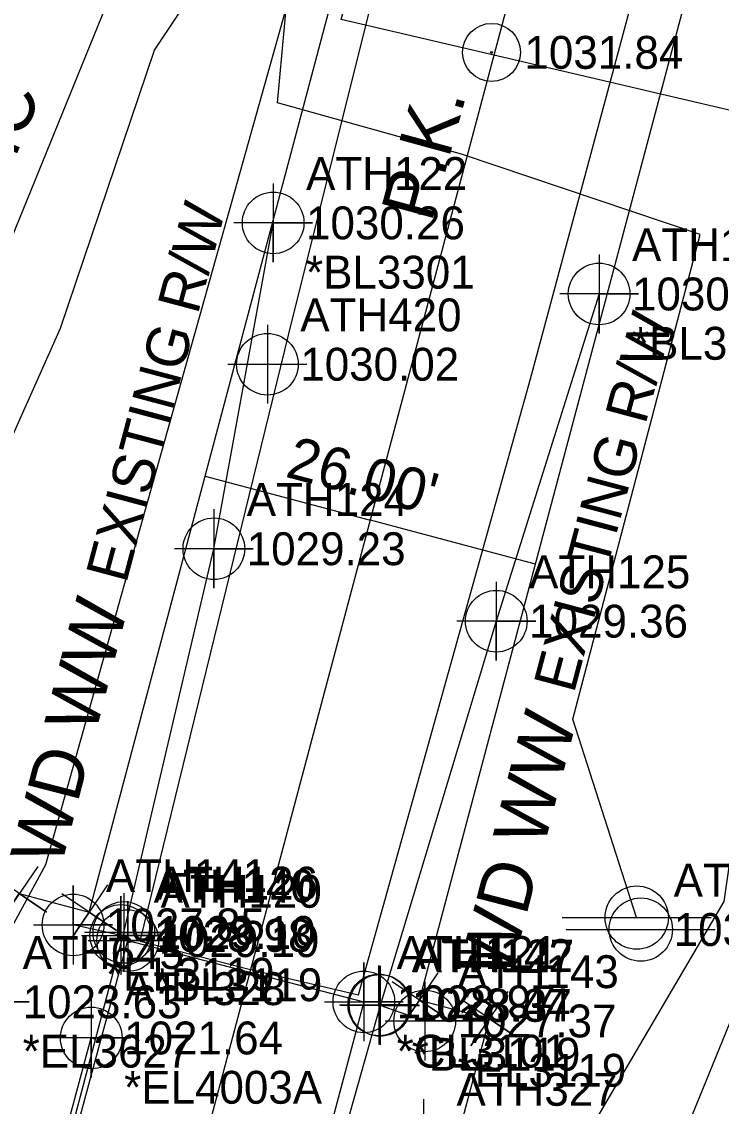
# Model space of a CAD drawing. Extents: x 1212084 to 1214478, y 765637 to 767408.
# Drawn here: x 1213319 to 1213372.2, y 766500.6 to 766583.1 of the extents above; entities that cross this region are included whole.
import ezdxf

# ---------------------------------------------------------------- set-up
doc = ezdxf.new("R2010")
doc.units = 0
for name, color, linetype in [('Cogo Default Point CELL', 7, 'Continuous'), ('COGO Default Point Elevation', 7, 'Continuous'), ('COGO Default Point Number', 7, 'Continuous'), ('Default', 7, 'Continuous'), ('Exist DTM Drainline', 7, 'Continuous'), ('Exist DTM Drainline Cogo Comment', 7, 'Continuous'), ('Exist DTM Drainline Cogo Elevation', 7, 'Continuous'), ('Exist DTM Drainline Cogo Number', 7, 'Continuous'), ('Exist DTM Drainline Cogo Point CELL', 7, 'Continuous'), ('Exist Environmental Wetland Boundary Cogo Comment', 7, 'Continuous'), ('Exist Environmental Wetland Boundary Cogo Elevation', 7, 'Continuous'), ('Exist Environmental Wetland Boundary Cogo Number', 7, 'Continuous'), ('Exist Environmental Wetland Boundary Cogo Point CELL', 7, 'Continuous'), ('Exist Guardrail', 7, 'Continuous'), ('Exist Guardrail Cogo Comment', 7, 'Continuous'), ('Exist Guardrail Cogo Elevation', 7, 'Continuous'), ('Exist Guardrail Cogo Number', 7, 'Continuous'), ('Exist Guardrail Cogo Point CELL', 7, 'Continuous'), ('Exist Horizontal Alignment', 7, 'Continuous'), ('Exist Hydro Stream or Body of Water', 7, 'Continuous'), ('Exist Other Culture Fence Line', 7, 'Continuous'), ('Exist Other Culture Fence Line Text', 7, 'Continuous'), ('Exist Property Corner CELL', 7, 'Continuous'), ('Exist Property Iron Pin CELL', 7, 'Continuous'), ('Exist Property Iron Pin Cogo Elevation', 7, 'Continuous'), ('Exist Property Iron Pin Text', 7, 'Continuous'), ('Exist Right of Way Line', 7, 'Continuous'), ('Exist Right of Way Line Text', 7, 'Continuous'), ('Exist Right of Way Width CELL', 7, 'Continuous'), ('Exist Roads EOP', 7, 'Continuous'), ('Exist Structure Major Bridge WW', 7, 'Continuous'), ('Exist Structure Major Bridge WW Cogo Comment', 7, 'Continuous'), ('Exist Structure Major Bridge WW Cogo Elevation', 7, 'Continuous'), ('Exist Structure Major Bridge WW Cogo Number', 7, 'Continuous'), ('Exist Structure Major Bridge WW Cogo Point CELL', 7, 'Continuous'), ('Exist Structure Major Bridge WW Text', 7, 'Continuous'), ('Exist Structure Major Deck Tunnel Box Culvert', 7, 'Continuous'), ('Exist Structure Major Deck Tunnel Box Culvert Cogo Comment', 7, 'Continuous'), ('Exist Structure Major Deck Tunnel Box Culvert Cogo Elevation', 7, 'Continuous'), ('Exist Structure Major Deck Tunnel Box Culvert Cogo Number', 7, 'Continuous'), ('Exist Structure Major Deck Tunnel Box Culvert Cogo Point CELL', 7, 'Continuous'), ('Exist Utilities Telephone Pole CELL', 7, 'Continuous'), ('Exist Utilities Telephone Pole Cogo Elevation', 7, 'Continuous'), ('Exist Utilities Telephone Pole Cogo Number', 7, 'Continuous'), ('Exist Utilities Telephone UG Cable SUE LOS C', 7, 'Continuous'), ('Exist Utilities Water UG Line SUE LOS B', 7, 'Continuous'), ('Exist Vegetation Woods Line', 7, 'Continuous')]:
    doc.layers.add(name, color=color, linetype=linetype)

# ---------------------------------------------------------------- blocks, each defined once
blk = doc.blocks.new('POINT_DISPLAY')
at = {"layer": 'Default'}
blk.add_line((0, 0), (0, 0), dxfattribs=at)
blk = doc.blocks.new('POINT')
at = {"layer": 'Default'}
blk.add_blockref('POINT_DISPLAY', (0, 0), dxfattribs=at)

msp = doc.modelspace()

# ---------------------------------------------------------------- linework, layer by layer
at = {"layer": 'Cogo Default Point CELL'}
for points in [[(1213337.641, 766560.024), (1213337.641, 766557.024)], [(1213334.641, 766557.024), (1213337.641, 766557.024)], [(1213337.641, 766557.024), (1213340.641, 766557.024)], [(1213337.641, 766557.024), (1213337.641, 766554.024)]]:
    msp.add_lwpolyline(points, dxfattribs=at)
msp.add_circle((1213337.641, 766557.024), 2.344, dxfattribs=at)
at = {"layer": 'Exist DTM Drainline'}
msp.add_lwpolyline([(1213324.525, 766505.694), (1213324.243, 766505.779)], dxfattribs=at)
at = {"layer": 'Exist DTM Drainline Cogo Point CELL'}
for points in [[(1213324.243, 766508.779), (1213324.243, 766502.779), (1213324.243, 766505.779), (1213327.243, 766505.779), (1213321.243, 766505.779)], [(1213349.519, 766501.124), (1213349.519, 766495.124), (1213349.519, 766498.124), (1213352.519, 766498.124), (1213346.519, 766498.124)]]:
    msp.add_lwpolyline(points, dxfattribs=at)
msp.add_circle((1213324.243, 766505.779), 2.344, dxfattribs=at)
at = {"layer": 'Exist Environmental Wetland Boundary Cogo Point CELL'}
msp.add_lwpolyline([(1213316.525, 766511.528), (1213316.525, 766505.528), (1213316.525, 766508.528), (1213319.525, 766508.528), (1213313.525, 766508.528)], dxfattribs=at)
at = {"layer": 'Exist Guardrail'}
for points in [[(1213320.009, 766488.433), (1213326.72, 766513.805), (1213333.566, 766542.99), (1213338.078, 766567.775)], [(1213362.87, 766562.366), (1213355.045, 766537.48), (1213346.209, 766508.26), (1213338.987, 766482.638)]]:
    msp.add_lwpolyline(points, dxfattribs=at)
at = {"layer": 'Exist Guardrail Cogo Point CELL'}
for points in [[(1213338.078, 766570.775), (1213338.078, 766564.775), (1213338.078, 766567.775), (1213341.078, 766567.775), (1213335.078, 766567.775)], [(1213362.87, 766565.366), (1213362.87, 766559.366), (1213362.87, 766562.366), (1213365.87, 766562.366), (1213359.87, 766562.366)], [(1213333.566, 766545.99), (1213333.566, 766539.99), (1213333.566, 766542.99), (1213336.566, 766542.99), (1213330.566, 766542.99)], [(1213355.045, 766540.48), (1213355.045, 766534.48), (1213355.045, 766537.48), (1213358.045, 766537.48), (1213352.045, 766537.48)], [(1213326.72, 766516.805), (1213326.72, 766510.805), (1213326.72, 766513.805), (1213329.72, 766513.805), (1213323.72, 766513.805)], [(1213346.209, 766511.26), (1213346.209, 766505.26), (1213346.209, 766508.26), (1213349.209, 766508.26), (1213343.209, 766508.26)]]:
    msp.add_lwpolyline(points, dxfattribs=at)
for centre in [(1213338.078, 766567.775), (1213362.87, 766562.366), (1213333.566, 766542.99), (1213355.045, 766537.48), (1213326.72, 766513.805), (1213346.209, 766508.26)]:
    msp.add_circle(centre, 2.344, dxfattribs=at)
at = {"layer": 'Exist Horizontal Alignment'}
msp.add_line((1213325.781, 766471.18), (1213367.554, 766628.175), dxfattribs=at)
at = {"layer": 'Exist Hydro Stream or Body of Water'}
msp.add_line((1213319.329, 766487.569), (1213324.243, 766505.779), dxfattribs=at)
at = {"layer": 'Exist Other Culture Fence Line'}
msp.add_lwpolyline([(1213233.32, 766620.626), (1213262.701, 766616.745), (1213306.285, 766606.368), (1213326.505, 766587.151), (1213300.794, 766523.955)], dxfattribs=at)
at = {"layer": 'Exist Property Corner CELL'}
for p, q in [((1213324.08, 766515.346), (1213324.08, 766515.346)), ((1213349.206, 766508.66), (1213349.206, 766508.66)), ((1213349.206, 766508.66), (1213349.206, 766508.66)), ((1213354.521, 766507.246), (1213354.521, 766507.246)), ((1213354.521, 766507.246), (1213354.521, 766507.246))]:
    msp.add_line(p, q, dxfattribs=at)
for points in [[(1213320.166, 766518.831), (1213317.365, 766514.689), (1213318.765, 766516.76), (1213320.836, 766515.359), (1213316.695, 766518.161)], [(1213325.481, 766517.416), (1213322.68, 766513.275), (1213324.08, 766515.346), (1213326.151, 766513.945), (1213322.01, 766516.746)], [(1213350.607, 766510.731), (1213347.806, 766506.589), (1213349.206, 766508.66), (1213351.277, 766507.259), (1213347.135, 766510.061)], [(1213350.607, 766510.731), (1213347.806, 766506.589), (1213349.206, 766508.66), (1213351.277, 766507.259), (1213347.135, 766510.061)], [(1213355.922, 766509.317), (1213353.121, 766505.175), (1213354.521, 766507.246), (1213356.592, 766505.845), (1213352.451, 766508.647)], [(1213355.922, 766509.317), (1213353.121, 766505.175), (1213354.521, 766507.246), (1213356.592, 766505.845), (1213352.451, 766508.647)]]:
    msp.add_lwpolyline(points, dxfattribs=at)
at = {"layer": 'Exist Property Iron Pin CELL'}
for radius in [2.203, 0.0707]:
    msp.add_circle((1213354.691, 766580.743), radius, dxfattribs=at)
at = {"layer": 'Exist Right of Way Line'}
for p, q in [((1213324.08, 766515.346), (1213354.991, 766631.517)), ((1213349.206, 766508.66), (1213380.117, 766624.832)), ((1213318.765, 766516.76), (1213324.08, 766515.346)), ((1213349.206, 766508.66), (1213354.521, 766507.246)), ((1213343.659, 766466.424), (1213354.521, 766507.246))]:
    msp.add_line(p, q, dxfattribs=at)
at = {"layer": 'Exist Right of Way Width CELL'}
for p in [(1213332.904, 766548.505), (1213358.029, 766541.82)]:
    msp.add_line(p, (1213345.39, 766545.183), dxfattribs=at)
at = {"layer": 'Exist Roads EOP'}
for points in [[(1213344.559, 766509.063), (1213357.659, 766555.924), (1213369.404, 766599.695), (1213380.499, 766635.509), (1213390.234, 766668.75)], [(1213327.952, 766513.134), (1213339.553, 766560.471), (1213350.847, 766605.718), (1213360.679, 766641.433)], [(1213327.952, 766513.134), (1213336.15, 766511.045), (1213344.559, 766509.063)]]:
    msp.add_lwpolyline(points, dxfattribs=at)
at = {"layer": 'Exist Structure Major Bridge WW'}
for p, q in [((1213326.487, 766513.577), (1213322.857, 766514.377)), ((1213346.114, 766508.293), (1213349.604, 766507.072))]:
    msp.add_line(p, q, dxfattribs=at)
at = {"layer": 'Exist Structure Major Bridge WW Cogo Point CELL'}
for points in [[(1213319.857, 766514.377), (1213325.857, 766514.377), (1213322.857, 766514.377), (1213322.857, 766517.377), (1213322.857, 766511.377)], [(1213323.487, 766513.577), (1213329.487, 766513.577), (1213326.487, 766513.577), (1213326.487, 766516.577), (1213326.487, 766510.577)], [(1213343.114, 766508.293), (1213349.114, 766508.293), (1213346.114, 766508.293), (1213346.114, 766511.293), (1213346.114, 766505.293)], [(1213346.604, 766507.072), (1213352.604, 766507.072), (1213349.604, 766507.072), (1213349.604, 766510.072), (1213349.604, 766504.072)]]:
    msp.add_lwpolyline(points, dxfattribs=at)
for centre in [(1213322.857, 766514.377), (1213326.487, 766513.577), (1213346.114, 766508.293), (1213349.604, 766507.072)]:
    msp.add_circle(centre, 2.344, dxfattribs=at)
at = {"layer": 'Exist Structure Major Deck Tunnel Box Culvert'}
msp.add_lwpolyline([(1213334.645, 766469.793), (1213316.583, 766474.725), (1213327.014, 766513.184), (1213344.974, 766508.526), (1213334.645, 766469.793)], dxfattribs=at)
at = {"layer": 'Exist Structure Major Deck Tunnel Box Culvert Cogo Point CELL'}
for points in [[(1213324.014, 766513.184), (1213330.014, 766513.184), (1213327.014, 766513.184), (1213327.014, 766516.184), (1213327.014, 766510.184)], [(1213341.974, 766508.526), (1213347.974, 766508.526), (1213344.974, 766508.526), (1213344.974, 766511.526), (1213344.974, 766505.526)]]:
    msp.add_lwpolyline(points, dxfattribs=at)
for centre in [(1213327.014, 766513.184), (1213344.974, 766508.526)]:
    msp.add_circle(centre, 2.344, dxfattribs=at)
at = {"layer": 'Exist Utilities Telephone Pole CELL'}
for p, q in [((1213360.056, 766514.936), (1213371.394, 766514.936)), ((1213365.731, 766514.936), (1213365.731, 766514.936)), ((1213360.364, 766514.025), (1213371.701, 766514.025)), ((1213366.039, 766514.025), (1213366.039, 766514.025))]:
    msp.add_line(p, q, dxfattribs=at)
for centre in [(1213365.731, 766514.936), (1213366.039, 766514.025)]:
    msp.add_circle(centre, 2.407, dxfattribs=at)
at = {"layer": 'Exist Utilities Telephone UG Cable SUE LOS C'}
msp.add_lwpolyline([(1213365.725, 766514.936), (1213360.871, 766530.037), (1213370.566, 766566.892), (1213352.413, 766572.994), (1213338.406, 766576.902), (1213340.189, 766596.206), (1213358.463, 766650.999), (1213381.885, 766733.254), (1213404.406, 766820.115), (1213404.353, 766820.096)], dxfattribs=at)
at = {"layer": 'Exist Utilities Water UG Line SUE LOS B'}
for points in [[(1213442.485, 766187.899), (1213413.61, 766239.451), (1213383.654, 766291.968), (1213352.36, 766345.759), (1213337.483, 766385.325), (1213335.947, 766431.182), (1213343.643, 766467.236), (1213372.392, 766516.172), (1213376.297, 766543.269), (1213379.468, 766574.764), (1213363.657, 766578.488), (1213343.259, 766583.25), (1213356.595, 766631.997), (1213369.551, 766678.004), (1213389.41, 766743.157), (1213404.898, 766797.922), (1213408.97, 766818.968)], [(1213312.252, 766356.682), (1213342.315, 766369.143), (1213353.998, 766372.079), (1213350.927, 766383.418), (1213347.777, 766424.606), (1213351.576, 766454.854), (1213376.387, 766515.679), (1213382.751, 766545.226), (1213385.129, 766575.512), (1213387.127, 766612.966), (1213395.365, 766676.737), (1213413.112, 766741.363), (1213427.394, 766793.323), (1213430.959, 766811.701)]]:
    msp.add_lwpolyline(points, dxfattribs=at)
at = {"layer": 'Exist Vegetation Woods Line'}
for points in [[(1213321.909, 766559.774), (1213329.044, 766580.902), (1213334.181, 766588.61), (1213339.033, 766584.042), (1213320.768, 766518.947), (1213308.496, 766496.393), (1213292.199, 766497.632)], [(1213218.886, 766546.641), (1213255.986, 766561.487), (1213283.668, 766547.783), (1213293.942, 766534.079), (1213309.923, 766532.937), (1213321.909, 766559.774)]]:
    msp.add_lwpolyline(points, dxfattribs=at)

# ---------------------------------------------------------------- block references
at = {"layer": 'Default', "xscale": 1.3123333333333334, "yscale": 1.3123333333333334}
msp.add_blockref('POINT', (1213354.492, 766580.755), dxfattribs=at)

# ---------------------------------------------------------------- texts
at = {"layer": 'COGO Default Point Elevation'}
msp.add_text('1030.02', height=2.5, dxfattribs=at).set_placement((1213340.141, 766555.774))
at = {"layer": 'COGO Default Point Number'}
msp.add_text('ATH420', height=2.5, dxfattribs=at).set_placement((1213340.141, 766559.524))
at = {"layer": 'Exist DTM Drainline Cogo Comment'}
msp.add_text('*EL4003A', height=2.5, dxfattribs=at).set_placement((1213326.743, 766500.779))
at = {"layer": 'Exist DTM Drainline Cogo Elevation'}
msp.add_text('1021.64', height=2.5, dxfattribs=at).set_placement((1213326.743, 766504.529))
at = {"layer": 'Exist DTM Drainline Cogo Number'}
for s, p in [('ATH328', (1213326.743, 766508.279)), ('ATH327', (1213352.019, 766500.624))]:
    msp.add_text(s, height=2.5, dxfattribs=at).set_placement(p)
at = {"layer": 'Exist Environmental Wetland Boundary Cogo Comment'}
msp.add_text('*EL3627', height=2.5, dxfattribs=at).set_placement((1213319.025, 766503.528))
at = {"layer": 'Exist Environmental Wetland Boundary Cogo Elevation'}
msp.add_text('1023.63', height=2.5, dxfattribs=at).set_placement((1213319.025, 766507.278))
at = {"layer": 'Exist Environmental Wetland Boundary Cogo Number'}
msp.add_text('ATH645', height=2.5, dxfattribs=at).set_placement((1213319.025, 766511.028))
at = {"layer": 'Exist Guardrail Cogo Comment'}
for s, p in [('*BL3301', (1213340.578, 766562.775)), ('*BL3301A', (1213365.37, 766557.366))]:
    msp.add_text(s, height=2.5, dxfattribs=at).set_placement(p)
at = {"layer": 'Exist Guardrail Cogo Elevation'}
for s, p in [('1030.26', (1213340.578, 766566.525)), ('1030.60', (1213365.37, 766561.116)), ('1029.23', (1213336.066, 766541.74)), ('1029.36', (1213357.545, 766536.23)), ('1029.10', (1213329.22, 766512.555)), ('1028.37', (1213348.709, 766507.01))]:
    msp.add_text(s, height=2.5, dxfattribs=at).set_placement(p)
at = {"layer": 'Exist Guardrail Cogo Number'}
for s, p in [('ATH122', (1213340.578, 766570.275)), ('ATH123', (1213365.37, 766564.866)), ('ATH124', (1213336.066, 766545.49)), ('ATH125', (1213357.545, 766539.98)), ('ATH126', (1213329.22, 766516.305)), ('ATH127', (1213348.709, 766510.76))]:
    msp.add_text(s, height=2.5, dxfattribs=at).set_placement(p)
at = {"layer": 'Exist Other Culture Fence Line Text'}
msp.add_text('4S ELECTRIC', height=4, rotation=67.86128, dxfattribs=at).set_placement((1213307.452, 766545.628))
at = {"layer": 'Exist Property Iron Pin Cogo Elevation'}
msp.add_text('1031.84', height=2.5, dxfattribs=at).set_placement((1213357.191, 766579.493))
at = {"layer": 'Exist Property Iron Pin Text'}
msp.add_text('P.K.', height=4, rotation=74.68447, dxfattribs=at).set_placement((1213350.106, 766567.735))
at = {"layer": 'Exist Right of Way Line Text'}
for p in [(1213326.893, 766540.276), (1213360.945, 766531.913)]:
    msp.add_text('EXISTING R/W', height=3.2, rotation=75.1, dxfattribs=at).set_placement(p)
at = {"layer": 'Exist Right of Way Width CELL'}
msp.add_text("26.00'", height=3.2, rotation=345.1, dxfattribs=at).set_placement((1213338.916, 766548.484))
at = {"layer": 'Exist Structure Major Bridge WW Cogo Comment'}
for s, p in [('*EL3119', (1213325.357, 766509.377)), ('*BL3119', (1213328.987, 766508.577)), ('*BL3119', (1213348.614, 766503.293)), ('*EL3119', (1213352.104, 766502.072))]:
    msp.add_text(s, height=2.5, dxfattribs=at).set_placement(p)
at = {"layer": 'Exist Structure Major Bridge WW Cogo Elevation'}
for s, p in [('1027.85', (1213325.357, 766513.127)), ('1028.98', (1213328.987, 766512.327)), ('1028.44', (1213348.614, 766507.043)), ('1027.37', (1213352.104, 766505.822))]:
    msp.add_text(s, height=2.5, dxfattribs=at).set_placement(p)
at = {"layer": 'Exist Structure Major Bridge WW Cogo Number'}
for s, p in [('ATH141', (1213325.357, 766516.877)), ('ATH140', (1213328.987, 766516.077)), ('ATH142', (1213348.614, 766510.793)), ('ATH143', (1213352.104, 766509.572))]:
    msp.add_text(s, height=2.5, dxfattribs=at).set_placement(p)
at = {"layer": 'Exist Structure Major Bridge WW Text'}
for p in [(1213321.932, 766518.685), (1213356.05, 766510.099)]:
    msp.add_text('WD WW', height=4, rotation=75.52752, dxfattribs=at).set_placement(p)
at = {"layer": 'Exist Structure Major Deck Tunnel Box Culvert Cogo Comment'}
msp.add_text('*CL3101', height=2.5, dxfattribs=at).set_placement((1213347.474, 766503.526))
at = {"layer": 'Exist Structure Major Deck Tunnel Box Culvert Cogo Elevation'}
for s, p in [('1029.19', (1213329.514, 766511.934)), ('1028.97', (1213347.474, 766507.276))]:
    msp.add_text(s, height=2.5, dxfattribs=at).set_placement(p)
at = {"layer": 'Exist Structure Major Deck Tunnel Box Culvert Cogo Number'}
for s, p in [('ATH120', (1213329.514, 766515.684)), ('ATH121', (1213347.474, 766511.026))]:
    msp.add_text(s, height=2.5, dxfattribs=at).set_placement(p)
at = {"layer": 'Exist Utilities Telephone Pole Cogo Elevation'}
msp.add_text('1030.57', height=2.5, dxfattribs=at).set_placement((1213368.539, 766512.775))
at = {"layer": 'Exist Utilities Telephone Pole Cogo Number'}
msp.add_text('ATH159', height=2.5, dxfattribs=at).set_placement((1213368.539, 766516.525))

doc.saveas('drawing.dxf')
